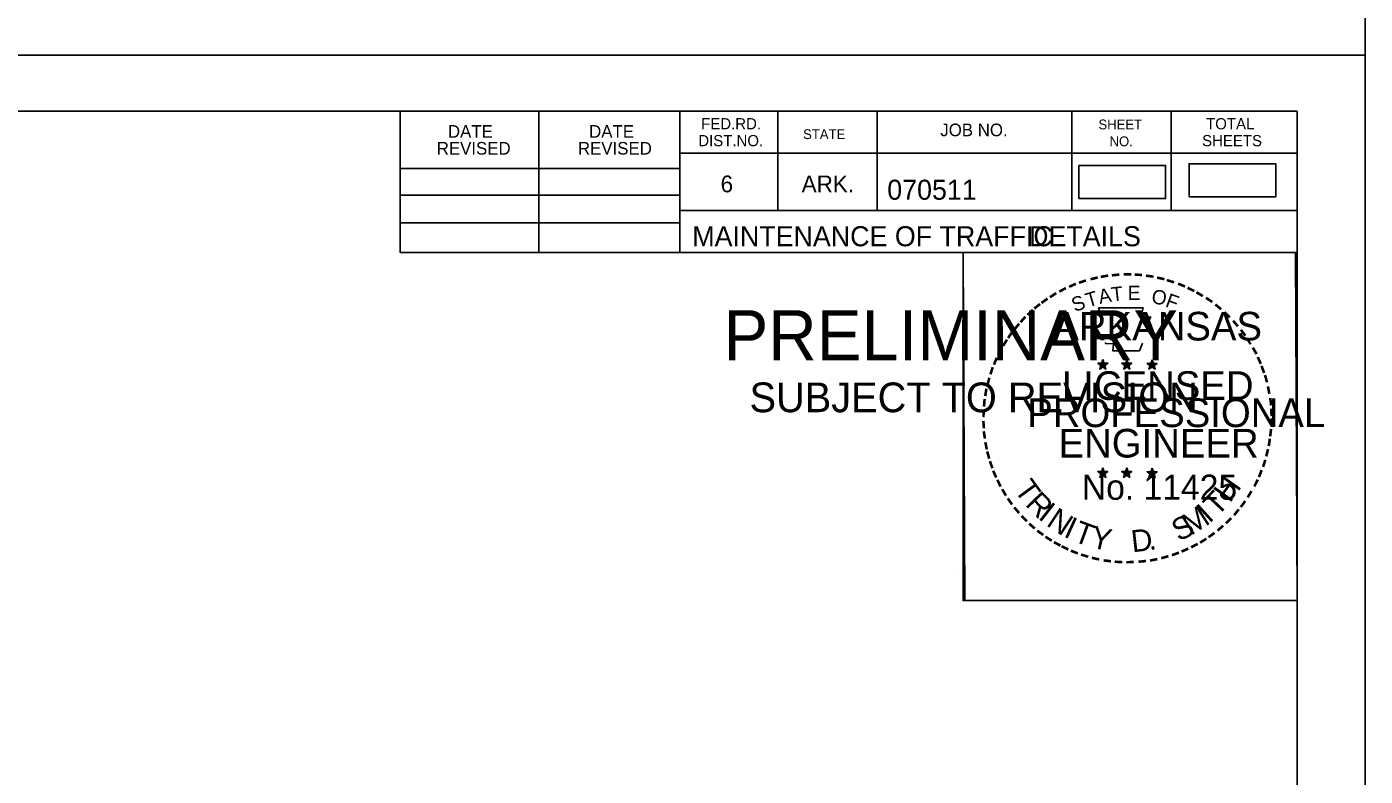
# Model space of a CAD drawing. Extents: x 1398460 to 1408037, y 380768 to 383968.
# Drawn here: x 1403531.6 to 1403998.9, y 381582.3 to 381844.2 of the extents above; entities that cross this region are included whole.
import ezdxf

# ---------------------------------------------------------------- set-up
doc = ezdxf.new("R2010")
doc.units = 0
for name, color, linetype in [('R_Border', 7, 'Continuous'), ('R_Border PE', 7, 'Continuous'), ('R_Border Prem', 7, 'Continuous'), ('R_Dimension', 7, 'Continuous'), ('R_No Plot', 7, 'Continuous')]:
    doc.layers.add(name, color=color, linetype=linetype)

msp = doc.modelspace()

# ---------------------------------------------------------------- linework, layer by layer
at = {"layer": 'R_Border'}
for p, q in [((1402394.27, 381814.73), (1403975.17, 381814.73)), ((1403661.97, 381765.33), (1403661.97, 381814.73)), ((1403710.37, 381765.33), (1403710.37, 381814.73)), ((1403759.67, 381814.73), (1403759.67, 381765.33)), ((1403793.87, 381814.73), (1403793.87, 381780.03)), ((1403828.57, 381814.73), (1403828.57, 381780.03)), ((1403896.47, 381814.73), (1403896.47, 381780.03)), ((1403931.17, 381814.73), (1403931.17, 381780.03)), ((1403975.17, 380787.43), (1403975.17, 381814.73)), ((1403975.17, 381800.03), (1403759.67, 381800.03)), ((1403975.17, 381800.13), (1403975.17, 381800.13)), ((1403661.97, 381794.63), (1403759.67, 381794.63)), ((1403661.97, 381785.33), (1403759.67, 381785.33)), ((1403975.17, 381780.03), (1403759.67, 381780.03)), ((1403774.47, 381780.03), (1403975.17, 381780.03)), ((1403661.97, 381775.63), (1403759.67, 381775.63)), ((1403975.17, 381765.33), (1403661.97, 381765.33))]:
    msp.add_line(p, q, dxfattribs=at)
at = {"layer": 'R_Border PE'}
for p, q in [((1403907.34, 381727.88), (1403907.13, 381726.62)), ((1403907.34, 381726.05), (1403907.34, 381727.88)), ((1403907.34, 381727.88), (1403907.58, 381726.63)), ((1403915.69, 381727.88), (1403915.48, 381726.62)), ((1403915.69, 381726.05), (1403915.69, 381727.88)), ((1403915.69, 381727.88), (1403915.93, 381726.63)), ((1403905.59, 381726.61), (1403907.34, 381726.05)), ((1403905.59, 381726.61), (1403906.86, 381726.38)), ((1403905.59, 381726.61), (1403906.78, 381726)), ((1403906.26, 381724.57), (1403907.34, 381726.05)), ((1403906.26, 381724.57), (1403906.89, 381725.79)), ((1403906.26, 381724.57), (1403907.33, 381725.65)), ((1403908.4, 381724.57), (1403907.33, 381725.64)), ((1403909.07, 381726.61), (1403907.34, 381726.05)), ((1403908.4, 381724.57), (1403907.34, 381726.05)), ((1403909.07, 381726.61), (1403907.64, 381726.36)), ((1403908.4, 381724.57), (1403907.72, 381726.02)), ((1403909.07, 381726.61), (1403908.05, 381726.1)), ((1403913.94, 381726.61), (1403915.69, 381726.05)), ((1403913.94, 381726.61), (1403915.21, 381726.38)), ((1403913.94, 381726.61), (1403915.13, 381726)), ((1403914.61, 381724.57), (1403915.69, 381726.05)), ((1403914.61, 381724.57), (1403915.24, 381725.79)), ((1403914.61, 381724.57), (1403915.68, 381725.65)), ((1403916.75, 381724.57), (1403915.68, 381725.64)), ((1403917.42, 381726.61), (1403915.69, 381726.05)), ((1403916.75, 381724.57), (1403915.69, 381726.05)), ((1403917.42, 381726.61), (1403915.99, 381726.36)), ((1403916.75, 381724.57), (1403916.07, 381726.02)), ((1403917.42, 381726.61), (1403916.4, 381726.1)), ((1403922.76, 381726.55), (1403924.51, 381725.99)), ((1403922.76, 381726.55), (1403924.03, 381726.32)), ((1403922.76, 381726.55), (1403923.95, 381725.94)), ((1403923.43, 381724.51), (1403924.51, 381725.99)), ((1403923.43, 381724.51), (1403924.06, 381725.73)), ((1403923.43, 381724.51), (1403924.5, 381725.59)), ((1403924.51, 381727.82), (1403924.3, 381726.56)), ((1403925.57, 381724.51), (1403924.5, 381725.58)), ((1403924.51, 381725.99), (1403924.51, 381727.82)), ((1403924.51, 381727.82), (1403924.75, 381726.57)), ((1403926.24, 381726.55), (1403924.51, 381725.99)), ((1403925.57, 381724.51), (1403924.51, 381725.99)), ((1403926.24, 381726.55), (1403924.81, 381726.3)), ((1403925.57, 381724.51), (1403924.89, 381725.96)), ((1403926.24, 381726.55), (1403925.22, 381726.04)), ((1403905.57, 381688.74), (1403907.32, 381688.19)), ((1403905.57, 381688.74), (1403906.84, 381688.52)), ((1403905.57, 381688.74), (1403906.76, 381688.13)), ((1403906.24, 381686.7), (1403907.32, 381688.19)), ((1403906.24, 381686.7), (1403906.87, 381687.92)), ((1403906.24, 381686.7), (1403907.31, 381687.79)), ((1403907.32, 381690.01), (1403907.11, 381688.75)), ((1403908.38, 381686.7), (1403907.31, 381687.77)), ((1403907.32, 381688.19), (1403907.32, 381690.01)), ((1403907.32, 381690.01), (1403907.56, 381688.76)), ((1403909.05, 381688.74), (1403907.32, 381688.19)), ((1403908.38, 381686.7), (1403907.32, 381688.19)), ((1403909.05, 381688.74), (1403907.62, 381688.5)), ((1403908.38, 381686.7), (1403907.7, 381688.16)), ((1403909.05, 381688.74), (1403908.03, 381688.23)), ((1403913.92, 381688.74), (1403915.66, 381688.19)), ((1403913.92, 381688.74), (1403915.18, 381688.52)), ((1403913.92, 381688.74), (1403915.1, 381688.13)), ((1403914.58, 381686.7), (1403915.66, 381688.19)), ((1403914.58, 381686.7), (1403915.21, 381687.92)), ((1403914.58, 381686.7), (1403915.65, 381687.79)), ((1403915.66, 381690.01), (1403915.46, 381688.75)), ((1403916.73, 381686.7), (1403915.65, 381687.77)), ((1403915.66, 381688.19), (1403915.66, 381690.01)), ((1403915.66, 381690.01), (1403915.91, 381688.76)), ((1403917.4, 381688.74), (1403915.66, 381688.19)), ((1403916.73, 381686.7), (1403915.66, 381688.19)), ((1403917.4, 381688.74), (1403915.97, 381688.5)), ((1403916.73, 381686.7), (1403916.04, 381688.16)), ((1403917.4, 381688.74), (1403916.38, 381688.23)), ((1403922.75, 381688.69), (1403924.5, 381688.14)), ((1403922.75, 381688.69), (1403924.02, 381688.47)), ((1403922.75, 381688.69), (1403923.94, 381688.08)), ((1403923.42, 381686.65), (1403924.5, 381688.14)), ((1403923.42, 381686.65), (1403924.05, 381687.87)), ((1403923.42, 381686.65), (1403924.49, 381687.74)), ((1403924.5, 381689.96), (1403924.29, 381688.7)), ((1403925.56, 381686.65), (1403924.49, 381687.72)), ((1403924.5, 381688.14), (1403924.5, 381689.96)), ((1403924.5, 381689.96), (1403924.74, 381688.71)), ((1403926.23, 381688.69), (1403924.5, 381688.14)), ((1403925.56, 381686.65), (1403924.5, 381688.14)), ((1403926.23, 381688.69), (1403924.8, 381688.45)), ((1403925.56, 381686.65), (1403924.88, 381688.11)), ((1403926.23, 381688.69), (1403925.21, 381688.18))]:
    msp.add_line(p, q, dxfattribs=at)
for points in [[(1403905.8, 381746), (1403907.14, 381741.86)], [(1403923.35, 381741.39), (1403924.06, 381742.81), (1403920.64, 381742.69), (1403921.38, 381746), (1403905.8, 381746)], [(1403908.26, 381733.88), (1403908.26, 381733.45), (1403911.07, 381733.35), (1403910.8, 381730.99), (1403920.15, 381730.99), (1403921.16, 381733.67)], [(1403907.34, 381727.88), (1403908.4, 381724.57), (1403905.59, 381726.61), (1403909.07, 381726.61), (1403906.26, 381724.57), (1403907.34, 381727.88)], [(1403915.69, 381727.88), (1403916.75, 381724.57), (1403913.94, 381726.61), (1403917.42, 381726.61), (1403914.61, 381724.57), (1403915.69, 381727.88)], [(1403924.51, 381727.82), (1403925.57, 381724.51), (1403922.76, 381726.55), (1403926.24, 381726.55), (1403923.43, 381724.51), (1403924.51, 381727.82)], [(1403907.32, 381690.01), (1403908.38, 381686.7), (1403905.57, 381688.74), (1403909.05, 381688.74), (1403906.24, 381686.7), (1403907.32, 381690.01)], [(1403915.66, 381690.01), (1403916.73, 381686.7), (1403913.92, 381688.74), (1403917.4, 381688.74), (1403914.58, 381686.7), (1403915.66, 381690.01)], [(1403924.5, 381689.96), (1403925.56, 381686.65), (1403922.75, 381688.69), (1403926.23, 381688.69), (1403923.42, 381686.65), (1403924.5, 381689.96)]]:
    msp.add_lwpolyline(points, dxfattribs=at)
for centre, radius in [((1403907.33, 381726.05), 0.861), ((1403907.33, 381726.05), 0.723), ((1403907.33, 381726.05), 0.579), ((1403907.33, 381726.05), 0.495), ((1403907.33, 381726.05), 0.374), ((1403907.33, 381726.05), 0.248), ((1403907.33, 381726.05), 0.148), ((1403915.68, 381726.05), 0.861), ((1403915.68, 381726.05), 0.723), ((1403915.68, 381726.05), 0.579), ((1403915.68, 381726.05), 0.495), ((1403915.68, 381726.05), 0.374), ((1403915.68, 381726.05), 0.248), ((1403915.68, 381726.05), 0.148), ((1403924.5, 381725.99), 0.861), ((1403924.5, 381725.99), 0.723), ((1403924.5, 381725.99), 0.579), ((1403924.5, 381725.99), 0.495), ((1403924.5, 381725.99), 0.374), ((1403924.5, 381725.99), 0.248), ((1403924.5, 381725.99), 0.148), ((1403907.31, 381688.18), 0.861), ((1403907.31, 381688.18), 0.723), ((1403907.31, 381688.18), 0.579), ((1403907.31, 381688.18), 0.495), ((1403907.31, 381688.18), 0.374), ((1403907.31, 381688.18), 0.248), ((1403907.31, 381688.18), 0.148), ((1403915.66, 381688.18), 0.861), ((1403915.66, 381688.18), 0.723), ((1403915.66, 381688.18), 0.579), ((1403915.66, 381688.18), 0.495), ((1403915.66, 381688.18), 0.374), ((1403915.66, 381688.18), 0.248), ((1403915.66, 381688.18), 0.148), ((1403924.49, 381688.13), 0.861), ((1403924.49, 381688.13), 0.723), ((1403924.49, 381688.13), 0.579), ((1403924.49, 381688.13), 0.495), ((1403924.49, 381688.13), 0.374), ((1403924.49, 381688.13), 0.248), ((1403924.49, 381688.13), 0.148)]:
    msp.add_circle(centre, radius, dxfattribs=at)
at = {"layer": 'R_Dimension'}
for points in [[(1403898.96, 381784.13), (1403929.23, 381784.13), (1403929.23, 381795.68), (1403898.96, 381795.68)], [(1403937.44, 381784.76), (1403967.71, 381784.76), (1403967.71, 381796.32), (1403937.44, 381796.32)]]:
    msp.add_lwpolyline(points, close=True, dxfattribs=at)
at = {"layer": 'R_No Plot'}
for p, q in [((1402332.26, 381834.22), (1403998.93, 381834.22)), ((1402332.26, 381834.2), (1403998.93, 381834.2)), ((1403855.34, 381653.05), (1403855.34, 381653.05))]:
    msp.add_line(p, q, dxfattribs=at)
for points in [[(1402332.23, 382900.89), (1403998.93, 382900.89), (1403998.93, 381834.2), (1402332.23, 381834.2)], [(1402332.23, 381834.2), (1403998.93, 381834.2), (1403998.93, 380767.52), (1402332.23, 380767.52)], [(1402394.27, 381814.73), (1402394.27, 380787.43), (1403975.17, 380787.43), (1403975.17, 381643.67), (1403858.52, 381643.67), (1403858.52, 381765.33), (1403661.97, 381765.33), (1403661.97, 381814.73)], [(1403563.87, 381814.73), (1403661.97, 381814.73), (1403661.97, 381765.33), (1403742.53, 381765.33), (1403858.52, 381765.33), (1403858.52, 381643.67), (1403975.17, 381643.67), (1403975.17, 380787.43), (1402394.27, 380787.43), (1402394.27, 381814.73)], [(1403858.52, 381765.33), (1403974.56, 381765.33), (1403975.17, 381643.67), (1403859.13, 381643.67)]]:
    msp.add_lwpolyline(points, close=True, dxfattribs=at)

# ---------------------------------------------------------------- texts
at = {"layer": 'R_Border'}
for s, height, p in [('FED.RD.', 3.91, (1403767.07, 381808.33)), ('TOTAL', 3.91, (1403943.37, 381808.33)), ('DATE', 4.396, (1403678.66, 381805.41)), ('DATE', 4.396, (1403727.96, 381805.41)), ('STATE', 3.42, (1403802.67, 381804.93)), ('JOB NO.', 4.396, (1403850.57, 381805.93)), ('SHEET', 3.42, (1403905.77, 381808.33)), ('REVISED', 4.396, (1403674.76, 381799.51)), ('REVISED', 4.396, (1403724.06, 381799.51)), ('DIST.NO.', 3.91, (1403766.07, 381802.43)), ('NO.', 3.42, (1403909.67, 381802.43)), ('SHEETS', 3.91, (1403941.97, 381802.43)), ('6', 5.86, (1403773.87, 381786.33)), ('ARK.', 5.861, (1403802.17, 381786.33)), ('070511', 7, (1403832.05, 381783.73)), ('MAINTENANCE OF TRAFFIC', 7, (1403763.98, 381767.48)), (' DETAILS', 7, (1403878.98, 381767.48))]:
    msp.add_text(s, height=height, dxfattribs=at).set_placement(p)
at = {"layer": 'R_Border PE'}
for s, height, rotation, p in [('-', 8, 19.1761, (1403899.54, 381751.63)), ('-', 8, 13.6302, (1403903.29, 381752.84)), ('-', 8, 10.2193, (1403906.68, 381753.65)), ('-', 8, 5.8968, (1403910.32, 381754.2)), ('-', 8, 0.1862, (1403914.18, 381754.56)), ('-', 8, 357.743, (1403917.8, 381754.49)), ('-', 8, 352.1617, (1403921.52, 381754.21)), ('-', 8, 347.2049, (1403925.11, 381753.64)), ('-', 8, 342.3362, (1403928.29, 381752.87)), ('-', 8, 34.0636, (1403890.22, 381746.85)), ('-', 8, 28.7918, (1403893.2, 381748.7)), ('-', 8, 24.3072, (1403896.37, 381750.29)), ('T', 5, 16.4036, (1403902.14, 381746.04)), ('A', 5, 11.2132, (1403906.27, 381747.3)), ('T', 5, 6.0228, (1403910.52, 381748.13)), ('E', 5, 0.8323, (1403916.04, 381748.68)), ('O', 5, 350.4515, (1403924.06, 381747.63)), ('-', 8, 337.8551, (1403931.96, 381751.75)), ('-', 8, 334.1211, (1403935.12, 381750.4)), ('-', 8, 329.6409, (1403938.01, 381748.98)), ('-', 8, 38.9507, (1403884.95, 381742.99)), ('-', 8, 36.2317, (1403887.33, 381744.88)), ('S', 5, 21.594, (1403897.57, 381744.39)), ('F', 5, 340.0707, (1403928.83, 381746.49)), ('-', 8, 325.8627, (1403941.23, 381747.18)), ('-', 8, 320.5297, (1403944.28, 381745.05)), ('-', 8, 48.4231, (1403880.54, 381738.51)), ('-', 8, 42.9622, (1403882.78, 381740.9)), ('-', 8, 315.5786, (1403947.27, 381742.61)), ('-', 8, 54.2325, (1403876.46, 381733.25)), ('-', 8, 50.6142, (1403878.53, 381736.08)), ('-', 8, 309.8797, (1403950.12, 381739.86)), ('-', 8, 306.6522, (1403952.74, 381736.85)), ('-', 8, 58.0706, (1403874.84, 381730.61)), ('-', 7, 303.6753, (1403955.17, 381734.01)), ('-', 8, 67.7743, (1403871.98, 381724.49)), ('-', 8, 62.8713, (1403873.27, 381727.54)), ('-', 8, 299.6684, (1403956.77, 381730.97)), ('-', 8, 294.6628, (1403958.39, 381727.91)), ('-', 8, 72.3945, (1403870.88, 381721.34)), ('-', 8, 290.5728, (1403959.67, 381725.03)), ('-', 8, 75.461, (1403869.9, 381717.77)), ('-', 8, 285.1233, (1403960.84, 381722.13)), ('-', 8, 280.5493, (1403961.84, 381718.42)), ('-', 8, 85.1863, (1403868.86, 381710.75)), ('-', 8, 81.2013, (1403869.24, 381714.2)), ('-', 8, 276.5962, (1403962.65, 381714.58)), ('-', 8, 89.0622, (1403868.73, 381707.24)), ('-', 8, 274.3301, (1403962.95, 381710.97)), ('-', 8, 94.1959, (1403868.91, 381703.62)), ('-', 8, 269.9407, (1403963.12, 381707.81)), ('-', 8, 98.9479, (1403869.27, 381700.28)), ('-', 8, 260.9953, (1403962.67, 381701.21)), ('-', 8, 263.5172, (1403963.03, 381704.48)), ('-', 8, 101.7149, (1403869.94, 381696.62)), ('-', 8, 105.4578, (1403870.75, 381693.64)), ('-', 8, 255.7626, (1403962.12, 381697.82)), ('-', 8, 109.0874, (1403871.83, 381690.49)), ('-', 8, 252.8681, (1403961.22, 381694.22)), ('-', 8, 114.0643, (1403873.1, 381687.51)), ('-', 8, 115.7289, (1403874.62, 381684.42)), ('T', 7.7, 306.0406, (1403876.11, 381682.38)), ('H', 7.7, 54.6088, (1403951.71, 381677.55)), ('-', 8, 244.6197, (1403958.79, 381687.71)), ('-', 8, 247.8887, (1403960.1, 381690.85)), ('-', 8, 120.4471, (1403876.41, 381681.49)), ('R', 7.7, 314.005, (1403879.93, 381677.14)), ('T', 7.7, 46.6444, (1403947.27, 381672.84)), ('-', 8, 239.0712, (1403956.82, 381683.95)), ('-', 8, 125.8934, (1403878.42, 381678.68)), ('-', 8, 130.7181, (1403880.73, 381675.92)), ('I', 7.7, 321.9694, (1403884.43, 381672.48)), ('M', 7.7, 32.6563, (1403938.04, 381666.22)), ('I', 7.7, 42.1136, (1403944.46, 381670.45)), ('-', 8, 233.8452, (1403954.81, 381680.68)), ('-', 8, 134.2238, (1403883.32, 381673.2)), ('N', 7.7, 326.5002, (1403887.26, 381670.12)), ('I', 7.7, 335.3603, (1403893.31, 381666.19)), ('S', 7.7, 26.9312, (1403933.84, 381664.19)), ('-', 8, 225.7653, (1403950.27, 381675.03)), ('-', 8, 231.2538, (1403952.66, 381677.85)), ('-', 8, 138.9338, (1403885.94, 381670.88)), ('-', 8, 144.6463, (1403888.72, 381668.85)), ('T', 7.7, 339.8912, (1403896.61, 381664.55)), ('Y', 7.7, 347.8556, (1403902.7, 381662.33)), ('D', 7.7, 6.3969, (1403917.62, 381660.53)), ('-', 8, 215.7363, (1403944.91, 381670.13)), ('-', 8, 221.0851, (1403947.66, 381672.49)), ('-', 8, 148.0898, (1403891.53, 381666.99)), ('-', 8, 151.5704, (1403894.42, 381665.37)), ('-', 8, 154.6002, (1403897.03, 381664.13)), ('.', 7.7, 13.7642, (1403923.58, 381661.17)), ('-', 8, 207.3568, (1403939.45, 381666.46)), ('-', 8, 212.2491, (1403942.24, 381668.19)), ('-', 8, 158.5612, (1403900.15, 381662.86)), ('-', 8, 162.7983, (1403903.59, 381661.8)), ('-', 8, 167.5555, (1403907.16, 381660.98)), ('-', 8, 173.1155, (1403911.02, 381660.43)), ('-', 8, 185.8167, (1403922.53, 381660.64)), ('-', 8, 191.2858, (1403926.21, 381661.3)), ('-', 8, 195.4743, (1403929.85, 381662.29)), ('-', 8, 200.7184, (1403933.24, 381663.5)), ('-', 8, 204.2516, (1403936.33, 381664.87)), ('-', 8, 176.5183, (1403914.76, 381660.16)), ('-', 8, 181.5918, (1403918.48, 381660.26))]:
    msp.add_text(s, height=height, rotation=rotation, dxfattribs=at).set_placement(p)
for s, height, p in [('ARKANSAS', 10, (1403890.06, 381734.56)), ('LICENSED', 10, (1403893.05, 381713.81)), ('DWB', 0.05, (1403907.27, 381726.02)), ('DWB', 0.05, (1403915.62, 381726.02)), ('DWB', 0.05, (1403924.44, 381725.97)), ('PROFESSIONAL', 10, (1403880.93, 381704.29)), ('ENGINEER', 10, (1403891.87, 381693.67)), ('No. 11425', 8.785, (1403900, 381678.91)), ('DWB', 0.05, (1403907.25, 381688.16)), ('DWB', 0.05, (1403915.6, 381688.16)), ('DWB', 0.05, (1403924.43, 381688.11))]:
    msp.add_text(s, height=height, dxfattribs=at).set_placement(p)
at = {"layer": 'R_Border Prem'}
for s, height, p in [('PRELIMINARY', 17.5, (1403774.92, 381727.65)), ('DWB', 0.05, (1403778.66, 381736.89)), ('SUBJECT TO REVISION', 10.3756, (1403783.97, 381709.5))]:
    msp.add_text(s, height=height, dxfattribs=at).set_placement(p)

doc.saveas('drawing.dxf')
